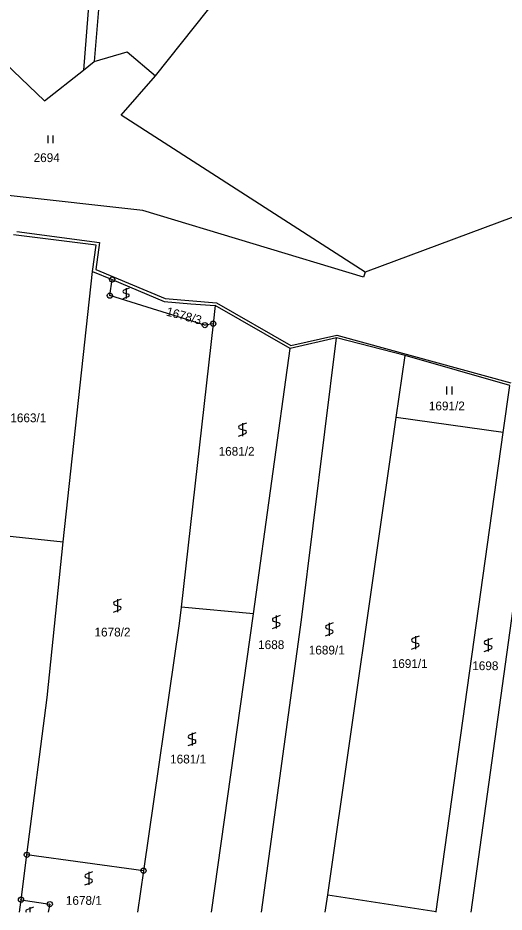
# Model space of a CAD drawing. Extents: x -600849 to -599899, y -1204328 to -1203436.
# Drawn here: x -600334.2 to -600240.2, y -1204325.4 to -1204152.5 of the extents above; entities that cross this region are included whole.
import ezdxf

# ---------------------------------------------------------------- set-up
doc = ezdxf.new("R2010")
doc.units = 0
for name, color, linetype in [('Vrstva 1', 7, 'Continuous'), ('Vrstva 2', 7, 'Continuous'), ('Vrstva 3', 7, 'Continuous'), ('Vrstva 4', 7, 'Continuous'), ('Vrstva 8', 7, 'Continuous')]:
    doc.layers.add(name, color=color, linetype=linetype)

msp = doc.modelspace()

# ---------------------------------------------------------------- linework, layer by layer
at = {"layer": 'Vrstva 1'}
for p, q in [((-600316, -1204088.53), (-600321.51, -1204162.57)), ((-600313.91, -1204091.03), (-600319.45, -1204160.92)), ((-600321.51, -1204162.57), (-600319.45, -1204160.92)), ((-600325.44, -1204253.81), (-600319.76, -1204201.49)), ((-600319.76, -1204201.49), (-600315.97, -1204203.08)), ((-600316.43, -1204206.19), (-600315.97, -1204203.08)), ((-600298.06, -1204211.9), (-600316.43, -1204206.19)), ((-600296.05, -1204208.11), (-600296.45, -1204211.62)), ((-600281.58, -1204216.41), (-600296.05, -1204208.11)), ((-600296.45, -1204211.62), (-600302.67, -1204266.42)), ((-600296.45, -1204211.62), (-600298.06, -1204211.9)), ((-600272.65, -1204214.38), (-600281.58, -1204216.41)), ((-600259.36, -1204217.8), (-600272.65, -1204214.38)), ((-600288.64, -1204267.71), (-600281.58, -1204216.41)), ((-600261.07, -1204229.75), (-600259.36, -1204217.8)), ((-600239.12, -1204223.6), (-600259.36, -1204217.8)), ((-600240.39, -1204232.69), (-600239.12, -1204223.6)), ((-600246.61, -1204325.42), (-600232.7, -1204224.81)), ((-600274.31, -1204322.09), (-600261.07, -1204229.75)), ((-600240.39, -1204232.69), (-600261.07, -1204229.75)), ((-600253.35, -1204325.3), (-600240.39, -1204232.69)), ((-600346.68, -1204251.52), (-600325.44, -1204253.81)), ((-600288.64, -1204267.71), (-600302.67, -1204266.42)), ((-600296.79, -1204325.42), (-600288.64, -1204267.71)), ((-600333.6, -1204323.02), (-600332.48, -1204314.33)), ((-600309.93, -1204317.41), (-600332.48, -1204314.33)), ((-600309.93, -1204317.41), (-600311.09, -1204325.42)), ((-600274.79, -1204325.42), (-600274.31, -1204322.09)), ((-600274.31, -1204322.09), (-600253.35, -1204325.3)), ((-600333.91, -1204325.42), (-600333.6, -1204323.02)), ((-600253.37, -1204325.42), (-600253.35, -1204325.3))]:
    msp.add_line(p, q, dxfattribs=at)
for points in [[(-600307.62, -1204163.7), (-600261.88, -1204106.1), (-600233.23, -1204089.94)], [(-599904.37, -1204110.11), (-599971.37, -1204166.99), (-600000.04, -1204221.75), (-600033.88, -1204211.2), (-600212.87, -1204181.45), (-600267.07, -1204201.63)], [(-600345.82, -1204152.51), (-600329.08, -1204168.52), (-600321.51, -1204162.57)], [(-600319.45, -1204160.92), (-600313.08, -1204159.01), (-600307.62, -1204163.7)], [(-600267.07, -1204201.63), (-600314.23, -1204171.27), (-600307.62, -1204163.7)], [(-600267.07, -1204201.63), (-600267.4, -1204202.64), (-600310.04, -1204189.73), (-600336.08, -1204186.84)], [(-600319.76, -1204201.49), (-600319.08, -1204196.44), (-600335.06, -1204194.4)], [(-600315.97, -1204203.08), (-600305.96, -1204207.3), (-600300.78, -1204207.75), (-600296.05, -1204208.11)], [(-600287.14, -1204325.42), (-600279.38, -1204268.86), (-600272.65, -1204214.38)], [(-600332.48, -1204314.33), (-600328.57, -1204283.94), (-600325.44, -1204253.81)], [(-600302.67, -1204266.42), (-600303.03, -1204269.63), (-600309.93, -1204317.41)], [(-600333.6, -1204323.02), (-600328.05, -1204323.88), (-600328.34, -1204325.42)]]:
    msp.add_lwpolyline(points, dxfattribs=at)
at = {"layer": 'Vrstva 3'}
for p, q in [((-600328.38, -1204176.69), (-600328.38, -1204175.19)), ((-600327.38, -1204176.69), (-600327.38, -1204175.19)), ((-600312.69, -1204204.77), (-600313.73, -1204205.15)), ((-600313.29, -1204204.77), (-600313.29, -1204206.77)), ((-600313.89, -1204206.77), (-600312.85, -1204206.38)), ((-600313.73, -1204205.63), (-600312.85, -1204205.9)), ((-600251.29, -1204225.28), (-600251.29, -1204223.78)), ((-600250.29, -1204225.28), (-600250.29, -1204223.78)), ((-600290.04, -1204230.84), (-600291.34, -1204231.32)), ((-600290.79, -1204230.84), (-600290.79, -1204233.34)), ((-600291.54, -1204233.34), (-600290.24, -1204232.85)), ((-600291.34, -1204231.92), (-600290.24, -1204232.25)), ((-600314.23, -1204264.9), (-600315.53, -1204265.38)), ((-600314.98, -1204264.9), (-600314.98, -1204267.4)), ((-600315.73, -1204267.4), (-600314.43, -1204266.91)), ((-600315.53, -1204265.98), (-600314.43, -1204266.31)), ((-600283.52, -1204268.06), (-600284.82, -1204268.54)), ((-600284.82, -1204269.14), (-600283.72, -1204269.47)), ((-600284.27, -1204268.06), (-600284.27, -1204270.56)), ((-600285.02, -1204270.56), (-600283.72, -1204270.07)), ((-600273.26, -1204269.48), (-600274.56, -1204269.96)), ((-600274.56, -1204270.56), (-600273.46, -1204270.89)), ((-600274.01, -1204269.48), (-600274.01, -1204271.98)), ((-600274.76, -1204271.98), (-600273.46, -1204271.49)), ((-600256.62, -1204272.04), (-600257.92, -1204272.52)), ((-600257.37, -1204272.04), (-600257.37, -1204274.54)), ((-600242.55, -1204272.49), (-600243.85, -1204272.97)), ((-600243.3, -1204272.49), (-600243.3, -1204274.99)), ((-600258.12, -1204274.54), (-600256.82, -1204274.05)), ((-600257.92, -1204273.12), (-600256.82, -1204273.45)), ((-600243.85, -1204273.57), (-600242.75, -1204273.9)), ((-600244.05, -1204274.99), (-600242.75, -1204274.5)), ((-600299.79, -1204290.72), (-600301.09, -1204291.2)), ((-600300.54, -1204290.72), (-600300.54, -1204293.22)), ((-600301.29, -1204293.22), (-600299.99, -1204292.73)), ((-600301.09, -1204291.8), (-600299.99, -1204292.13)), ((-600319.77, -1204317.65), (-600321.07, -1204318.13)), ((-600320.52, -1204317.65), (-600320.52, -1204320.15)), ((-600321.07, -1204318.73), (-600319.97, -1204319.06)), ((-600321.27, -1204320.15), (-600319.97, -1204319.66)), ((-600331.17, -1204324.48), (-600332.47, -1204324.96)), ((-600331.92, -1204324.48), (-600331.92, -1204325.42))]:
    msp.add_line(p, q, dxfattribs=at)
for centre, radius, start, end in [((-600313.63, -1204205.39), 0.263, 113.579, 246.421), ((-600312.95, -1204206.14), 0.263, 293.574, 66.426), ((-600291.21, -1204231.62), 0.329, 113.579, 246.421), ((-600290.37, -1204232.55), 0.329, 293.574, 66.426), ((-600315.4, -1204265.68), 0.329, 113.579, 246.421), ((-600314.56, -1204266.61), 0.329, 293.574, 66.426), ((-600284.69, -1204268.84), 0.329, 113.579, 246.421), ((-600283.85, -1204269.77), 0.329, 293.574, 66.426), ((-600274.43, -1204270.26), 0.329, 113.579, 246.421), ((-600273.59, -1204271.19), 0.329, 293.574, 66.426), ((-600257.79, -1204272.82), 0.329, 113.579, 246.421), ((-600256.95, -1204273.75), 0.329, 293.574, 66.426), ((-600243.72, -1204273.27), 0.329, 113.579, 246.421), ((-600242.88, -1204274.2), 0.329, 293.574, 66.426), ((-600300.96, -1204291.5), 0.329, 113.579, 246.421), ((-600300.12, -1204292.43), 0.329, 293.574, 66.426), ((-600320.94, -1204318.43), 0.329, 113.579, 246.421), ((-600320.1, -1204319.36), 0.329, 293.574, 66.426), ((-600332.34, -1204325.26), 0.329, 113.579, 209.3535)]:
    msp.add_arc(centre, radius, start, end, dxfattribs=at)
at = {"layer": 'Vrstva 4'}
for p, q in [((-600334.44, -1204193.79), (-600318.44, -1204195.9)), ((-600318.44, -1204195.9), (-600319.14, -1204201.14)), ((-600319.14, -1204201.14), (-600305.77, -1204206.77)), ((-600305.77, -1204206.77), (-600295.83, -1204207.58)), ((-600295.83, -1204207.58), (-600281.43, -1204215.84)), ((-600281.43, -1204215.84), (-600272.57, -1204213.82)), ((-600272.57, -1204213.82), (-600238.93, -1204223.07))]:
    msp.add_line(p, q, dxfattribs=at)
at = {"layer": 'Vrstva 8'}
for centre, radius in [((-600315.97, -1204203.08), 0.5), ((-600315.97, -1204203.08), 0.0303), ((-600316.43, -1204206.19), 0.5), ((-600316.43, -1204206.19), 0.0303), ((-600298.06, -1204211.9), 0.5), ((-600298.06, -1204211.9), 0.0303), ((-600296.45, -1204211.62), 0.5), ((-600296.45, -1204211.62), 0.0303), ((-600332.48, -1204314.33), 0.5), ((-600332.48, -1204314.33), 0.0303), ((-600309.93, -1204317.41), 0.5), ((-600309.93, -1204317.41), 0.0303), ((-600333.6, -1204323.02), 0.5), ((-600333.6, -1204323.02), 0.0303), ((-600328.05, -1204323.88), 0.5), ((-600328.05, -1204323.88), 0.0303)]:
    msp.add_circle(centre, radius, dxfattribs=at)

# ---------------------------------------------------------------- texts
at = {"layer": 'Vrstva 2'}
for s, p in [('2694', (-600331.17, -1204180.36)), ('1691/2', (-600254.77, -1204228.38)), ('1663/1', (-600335.67, -1204230.68)), ('1681/2', (-600295.41, -1204237.15)), ('1678/2', (-600319.4, -1204272.11)), ('1688', (-600287.77, -1204274.55)), ('1689/1', (-600277.98, -1204275.59)), ('1691/1', (-600261.95, -1204278.2)), ('1698', (-600246.38, -1204278.62)), ('1681/1', (-600304.78, -1204296.67)), ('1678/1', (-600324.94, -1204324.01))]:
    msp.add_text(s, height=1.7, dxfattribs=at).set_placement(p)
msp.add_text('1678/3', height=1.7, rotation=345, dxfattribs=at).set_placement((-600305.67, -1204210.01))

doc.saveas('drawing.dxf')
